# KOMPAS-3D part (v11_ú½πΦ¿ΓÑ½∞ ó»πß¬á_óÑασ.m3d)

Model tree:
1. Эскиз:1
2. Операция вращения:1
     Угол 1 = 60; Угол 2 = 360
3. Скругление:1
     Радиус = 1.5

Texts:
  Линия-выноска #1
  Линия-выноска #2
  Линия-выноска #3
  Отклонения формы и база
  Марка координационной оси
  Марка/позиционное обозначение с линией-выноской
  Марка/позиционное обозначение на линии
  Марка/позиционное обозначение без линии-выноски
  Текст на чертеже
